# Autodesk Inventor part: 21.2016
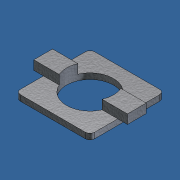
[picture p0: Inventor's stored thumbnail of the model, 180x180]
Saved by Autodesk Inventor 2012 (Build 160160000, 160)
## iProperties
Created: 2007-01
Part Number: 21.2016
Document SubType Name: Modeling
Designer: Andy Moles
Material: Aluminum-6061
Density: 2.71 g/cm^3
Mass: 6.76867 g
Surface Area: 23.7311 cm^2
Volume: 2.49766 cm^3
Description: ANTI-TWIST DEVICE
Vendor: S
Title: ANTI ROTATION DEVICE
Author: Andy Moles
Keywords: ANTI-ROTATION DEVICE FOR ANGLES
Comments: ANTI ROTATION DEVICE FOR ANGLES BRACKETS AND MANY MINITEC PARTS
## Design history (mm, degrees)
sketch "Sketch1"
  geometry: L1 (-14.25, -16.25)-(14.25, -16.25); L2 (16.25, -14.25)-(16.25, 14.25); L3 (14.25, 16.25)-(-14.25, 16.25); L4 (-16.25, 14.25)-(-16.25, -14.25); L5 (-16.25, -16.25)-(16.25, 16.25); A1 r 2 centre (-14.25, -14.25) between (-16.25, -14.25) and (-14.25, -16.25); A2 r 2 centre (14.25, -14.25) between (14.25, -16.25) and (16.25, -14.25); A3 r 2 centre (14.25, 14.25) between (16.25, 14.25) and (14.25, 16.25); A4 r 2 centre (-14.25, 14.25) between (-14.25, 16.25) and (-16.25, 14.25); 4 further points
  constraints: 10 end point, 8 point on circle, 8 point on line, 8 tangent, 4 centre point, 3 equal radius, 2 parallel, 1 coincident, 1 horizontal, 1 midpoint, 1 perpendicular
  dimensions: "d0" = 32.5 distance of point (-16.25, 16.25) L5.start; "d1" = 32.5 distance of L5.end point (-16.25, 16.25); "d9" = 2 radius of A1
extrude "Extrusion1" new body sketch "Sketch1" distance "d3" = 2.5; taper "d4" = 0 deg
sketch "Sketch2"
  geometry: L1 (-20.5, -4.1)-(20.5, -4.1); L2 (20.5, -4.1)-(20.5, 4.1); L3 (20.5, 4.1)-(-20.5, 4.1); L4 (-20.5, 4.1)-(-20.5, -4.1); L5 (20.5, -4.1)-(-20.5, 4.1); 2 further points
  constraints: 10 end point, 2 parallel, 1 coincident, 1 horizontal, 1 midpoint, 1 perpendicular
  dimensions: "d5" = 8.2 distance of L3.end L1.start; "d6" = 41 distance of L2.end L3.end
extrude "Extrusion2" join sketch "Sketch2" distance "d7" = 4; taper "d8" = 0 deg
sketch "Sketch3"
  geometry: C1 r 10.25 at (0, 0); 1 further point
  constraints: 1 centre point, 1 coincident
  dimensions: "d10" = 20.5 diameter of C1
extrude "Extrusion3" cut sketch "Sketch3" stored distance "d11" = 4; taper "d12" = 0 deg
body "Solid1"
